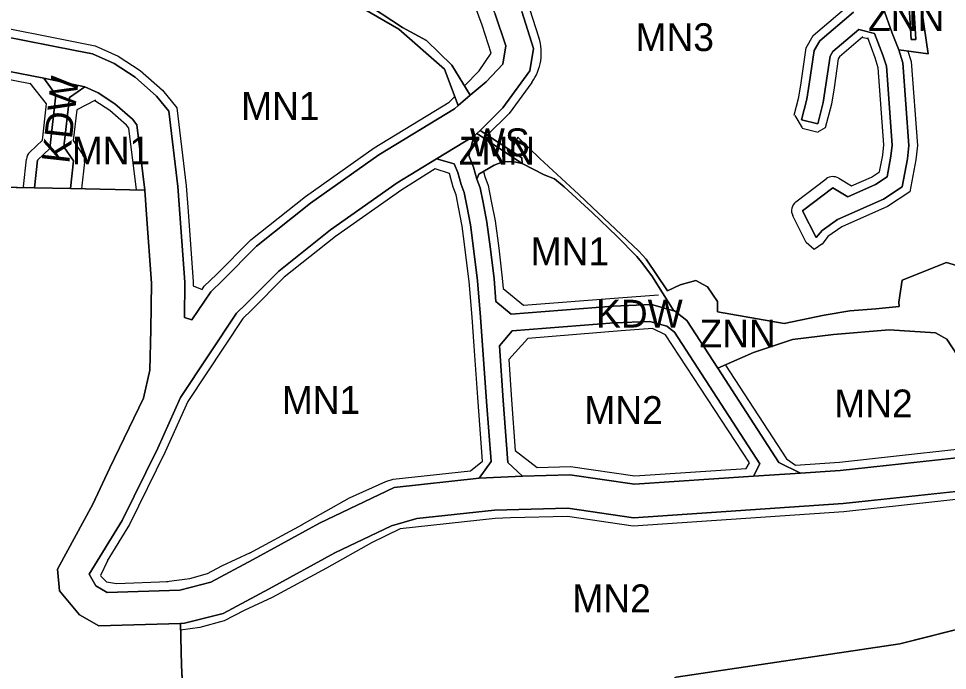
# Model space of a CAD drawing. Extents: x 7417187 to 7419415, y 5539178 to 5540826.
# Drawn here: x 7418734.7 to 7419069, y 5539426.9 to 5539661.6 of the extents above; entities that cross this region are included whole.
import ezdxf

# ---------------------------------------------------------------- set-up
doc = ezdxf.new("R2010")
doc.units = 0
for name, color, linetype in [('linie_rozgraniczajace', 7, 'Continuous'), ('linie_zabudowy_nieprzekraczalne', 7, 'Continuous'), ('linie_zabudowy_obowiazujace', 7, 'Continuous'), ('oznaczenia_przeznaczen', 7, 'Continuous')]:
    doc.layers.add(name, color=color, linetype=linetype)

msp = doc.modelspace()

# ---------------------------------------------------------------- linework, layer by layer
at = {"layer": 'linie_rozgraniczajace'}
for p, q in [((7418915.76, 5539664.18), (7418920.06, 5539650.87)), ((7418910.1, 5539651.81), (7418906.24, 5539663.18)), ((7418721.47, 5539656.75), (7418755.04, 5539650.17)), ((7418909.02, 5539645.17), (7418910.1, 5539651.81)), ((7418920.06, 5539650.87), (7418918.74, 5539642.86)), ((7418755.04, 5539650.17), (7418761.3, 5539648.92)), ((7418761.3, 5539648.92), (7418769.02, 5539645.39)), ((7418743.77, 5539640.15), (7418716.56, 5539645.49)), ((7418769.02, 5539645.39), (7418776.61, 5539640.53)), ((7418902.92, 5539638.89), (7418909.02, 5539645.17)), ((7418776.61, 5539640.53), (7418784.34, 5539633.71)), ((7418918.74, 5539642.86), (7418909.01, 5539629.45)), ((7418758.55, 5539636.99), (7418743.77, 5539640.15)), ((7418763.26, 5539634.83), (7418758.55, 5539636.99)), ((7418897.27, 5539634.04), (7418902.92, 5539638.89)), ((7418769.36, 5539630.92), (7418763.26, 5539634.83)), ((7418784.34, 5539633.71), (7418788.76, 5539628.29)), ((7418892.9, 5539630.28), (7418897.27, 5539634.04)), ((7418775.66, 5539625.36), (7418769.36, 5539630.92)), ((7418891.57, 5539629.14), (7418892.9, 5539630.28)), ((7418788.76, 5539628.29), (7418792.01, 5539601.11)), ((7418864.35, 5539612.52), (7418891.57, 5539629.14)), ((7418909.01, 5539629.45), (7418900.77, 5539621.35)), ((7418777.26, 5539623.4), (7418775.66, 5539625.36)), ((7418780.07, 5539599.87), (7418777.26, 5539623.4)), ((7418899.59, 5539620.2), (7418898.99, 5539619.61)), ((7418900.77, 5539621.35), (7418899.59, 5539620.2)), ((7418898.5, 5539619.31), (7418885.09, 5539611.12)), ((7418898.99, 5539619.61), (7418898.5, 5539619.31)), ((7418839.77, 5539595.13), (7418864.35, 5539612.52)), ((7418885.09, 5539611.12), (7418870.95, 5539602.49)), ((7418655.08, 5539602.38), (7418740.36, 5539600.67)), ((7418740.36, 5539600.67), (7418753.3, 5539600.41)), ((7418753.3, 5539600.41), (7418780.07, 5539599.87)), ((7418792.01, 5539601.11), (7418794.46, 5539566.73)), ((7418870.95, 5539602.49), (7418846.98, 5539585.52)), ((7418780.07, 5539599.87), (7418780.7, 5539591.09)), ((7418780.7, 5539591.09), (7418780.07, 5539599.87)), ((7418820.3, 5539579.65), (7418839.77, 5539595.13)), ((7418780.7, 5539591.09), (7418782.46, 5539566.36)), ((7418782.46, 5539566.36), (7418780.7, 5539591.09)), ((7418846.98, 5539585.52), (7418828.32, 5539570.69)), ((7418808.03, 5539567.3), (7418820.3, 5539579.65)), ((7418828.32, 5539570.69), (7418816.44, 5539558.74)), ((7418794.46, 5539566.73), (7418794.34, 5539553.92)), ((7418803.82, 5539563.26), (7418808.03, 5539567.3)), ((7418782.46, 5539566.36), (7418782.29, 5539549.7)), ((7418782.29, 5539549.7), (7418782.46, 5539566.36)), ((7418797.06, 5539553.11), (7418803.82, 5539563.26)), ((7418816.44, 5539558.74), (7418813.08, 5539555.51)), ((7418813.08, 5539555.51), (7418792.89, 5539525.21)), ((7418794.34, 5539553.92), (7418797.06, 5539553.11)), ((7418782.29, 5539549.7), (7418781.86, 5539535.02)), ((7418781.86, 5539535.02), (7418782.29, 5539549.7)), ((7418781.86, 5539535.02), (7418779.64, 5539524.96)), ((7418779.64, 5539524.96), (7418781.86, 5539535.02)), ((7418779.64, 5539524.96), (7418767.47, 5539499.83)), ((7418767.47, 5539499.83), (7418779.64, 5539524.96)), ((7418792.89, 5539525.21), (7418784.73, 5539506.91)), ((7418784.73, 5539506.91), (7418771.97, 5539480.92)), ((7419030.45, 5539498.89), (7419094.66, 5539505.83)), ((7418767.47, 5539499.83), (7418761.44, 5539486.71)), ((7418761.44, 5539486.71), (7418767.47, 5539499.83)), ((7418900.51, 5539496.09), (7418916.11, 5539496.87)), ((7418916.11, 5539496.87), (7418933.11, 5539497.3)), ((7418933.11, 5539497.3), (7418956.42, 5539493.92)), ((7418956.42, 5539493.92), (7418999.27, 5539496.8)), ((7418999.27, 5539496.8), (7419016.1, 5539497.93)), ((7419016.1, 5539497.93), (7419030.45, 5539498.89)), ((7418869.87, 5539492.74), (7418900.51, 5539496.09)), ((7419100.14, 5539494.37), (7419031.5, 5539486.94)), ((7418842.99, 5539479.9), (7418869.87, 5539492.74)), ((7418761.44, 5539486.71), (7418748.65, 5539463.29)), ((7418748.65, 5539463.29), (7418761.44, 5539486.71)), ((7419031.5, 5539486.94), (7418955.96, 5539481.86)), ((7418905.97, 5539484.62), (7418878, 5539481.56)), ((7418932.4, 5539485.28), (7418905.97, 5539484.62)), ((7418955.96, 5539481.86), (7418932.4, 5539485.28)), ((7418771.97, 5539480.92), (7418760.11, 5539461.57)), ((7418819.09, 5539466.85), (7418842.99, 5539479.9)), ((7418878, 5539481.56), (7418868.88, 5539478.97)), ((7418868.88, 5539478.97), (7418848.46, 5539469.21)), ((7418803.92, 5539458.61), (7418819.09, 5539466.85)), ((7418848.46, 5539469.21), (7418824.83, 5539456.31)), ((7418748.65, 5539463.29), (7418749.38, 5539455.54)), ((7418749.38, 5539455.54), (7418748.65, 5539463.29)), ((7418760.11, 5539461.57), (7418762.44, 5539457.29)), ((7418762.44, 5539457.29), (7418766.5, 5539454.99)), ((7418792.74, 5539455.79), (7418803.92, 5539458.61)), ((7418824.83, 5539456.31), (7418808.32, 5539447.35)), ((7418749.38, 5539455.54), (7418756.53, 5539446.85)), ((7418756.53, 5539446.85), (7418749.38, 5539455.54)), ((7418766.5, 5539454.99), (7418792.74, 5539455.79)), ((7418756.53, 5539446.85), (7418763.51, 5539442.89)), ((7418763.51, 5539442.89), (7418756.53, 5539446.85)), ((7418808.32, 5539447.35), (7418794.41, 5539443.84)), ((7418763.51, 5539442.89), (7418792.9, 5539443.79)), ((7418792.9, 5539443.79), (7418763.51, 5539442.89)), ((7418794.41, 5539443.84), (7418792.9, 5539443.79)), ((7418792.9, 5539443.79), (7418793.33, 5539428.77)), ((7419051.94, 5539436.41), (7419080.39, 5539443.66)), ((7418971.32, 5539424.46), (7419051.94, 5539436.41)), ((7418793.33, 5539428.77), (7418794.01, 5539413.71))]:
    msp.add_line(p, q, dxfattribs=at)
for points in [[(7419047.5, 5539744.86), (7419059.78, 5539708.29), (7419060.96, 5539690.25), (7419059.26, 5539677.84), (7419056.87, 5539667.66), (7419057.67, 5539654.15), (7419055.93, 5539654.12), (7419055.16, 5539667.82), (7419057.85, 5539679.27), (7419059.02, 5539686.28), (7419059.04, 5539692.28), (7419058.46, 5539703.84), (7419057.49, 5539709.17), (7419045.02, 5539745.28)], [(7418897.27, 5539634.04), (7418890.59, 5539644.9), (7418881.51, 5539653.71), (7418872.9, 5539658.41), (7418857.8, 5539668.36), (7418846.8, 5539675.56), (7418812.55, 5539679.73), (7418811.52, 5539682.26), (7418808.62, 5539698.53), (7418791.51, 5539718.25), (7418804.62, 5539739.12), (7418816.66, 5539735.33), (7418826.26, 5539733.2), (7418853.21, 5539731.33), (7418864.01, 5539731.44), (7418870.47, 5539726.74), (7418874.06, 5539718.28), (7418880.65, 5539707.8), (7418891.15, 5539691.67), (7418899.89, 5539677.74), (7418906.24, 5539663.18), (7418910.1, 5539651.81), (7418909.02, 5539645.17), (7418902.92, 5539638.89)], [(7418743.77, 5539640.15), (7418748.05, 5539634.12), (7418745.93, 5539614.83), (7418741.45, 5539610.61), (7418740.36, 5539600.67), (7418655.08, 5539602.38), (7418645.97, 5539602.68), (7418652.71, 5539652.14), (7418658.31, 5539656.29), (7418665.64, 5539654.94), (7418716.56, 5539645.49)], [(7418758.55, 5539636.99), (7418753.03, 5539633.15), (7418751, 5539615.45), (7418754.44, 5539610.34), (7418753.3, 5539600.41), (7418740.36, 5539600.67), (7418741.45, 5539610.61), (7418745.93, 5539614.83), (7418748.05, 5539634.12), (7418743.77, 5539640.15)], [(7418780.07, 5539599.87), (7418753.3, 5539600.41), (7418754.44, 5539610.34), (7418751, 5539615.45), (7418753.03, 5539633.15), (7418758.55, 5539636.99), (7418763.26, 5539634.83), (7418769.36, 5539630.92), (7418775.66, 5539625.36), (7418777.26, 5539623.4)], [(7418915.98, 5539609.46), (7418912.49, 5539610.13), (7418909.02, 5539609.99), (7418905.8, 5539608.84), (7418900.32, 5539605.65), (7418899.63, 5539603.75), (7418898.43, 5539608.09), (7418896.73, 5539612.29), (7418898.5, 5539619.31), (7418898.99, 5539619.61), (7418899.59, 5539620.2)], [(7418911.95, 5539613.98), (7418915.76, 5539611.47), (7418915.98, 5539609.46), (7418899.59, 5539620.2), (7418900.77, 5539621.35)], [(7418899.63, 5539603.75), (7418900.86, 5539600.71), (7418901.87, 5539595.36), (7418903.2, 5539588.32), (7418904.54, 5539578.57), (7418905.8, 5539567.85), (7418906.51, 5539559.76), (7418911.93, 5539555.17), (7418948.71, 5539558.04), (7418962.55, 5539558.6), (7418970.52, 5539556.38), (7418970.73, 5539556.32), (7418975.26, 5539552.89), (7418986.37, 5539535.74), (7419008.39, 5539501.79), (7419016.1, 5539497.93), (7418999.27, 5539496.8), (7419001.54, 5539501.33), (7418970.79, 5539548.74), (7418968.01, 5539550.85), (7418961.85, 5539552.57), (7418949.06, 5539552.05), (7418912.35, 5539549.18), (7418907.72, 5539543.81), (7418909.12, 5539524.11), (7418910.76, 5539501.76), (7418916.11, 5539496.87), (7418900.51, 5539496.09), (7418904.72, 5539502.06), (7418903.13, 5539523.68), (7418900.98, 5539554.12), (7418899.83, 5539567.24), (7418898.59, 5539577.81), (7418897.28, 5539587.36), (7418895.98, 5539594.24), (7418895.07, 5539599.01), (7418893.94, 5539601.82), (7418892.74, 5539606.16), (7418891.45, 5539609.35), (7418885.09, 5539611.12), (7418898.5, 5539619.31), (7418896.73, 5539612.29), (7418898.43, 5539608.09)], [(7418900.51, 5539496.09), (7418869.87, 5539492.74), (7418842.99, 5539479.9), (7418819.09, 5539466.85), (7418803.92, 5539458.61), (7418792.74, 5539455.79), (7418766.5, 5539454.99), (7418762.44, 5539457.29), (7418760.11, 5539461.57), (7418771.97, 5539480.92), (7418784.73, 5539506.91), (7418792.89, 5539525.21), (7418813.08, 5539555.51), (7418816.44, 5539558.74), (7418828.32, 5539570.69), (7418846.98, 5539585.52), (7418870.95, 5539602.49), (7418885.09, 5539611.12), (7418891.45, 5539609.35), (7418892.74, 5539606.16), (7418893.94, 5539601.82), (7418895.07, 5539599.01), (7418895.98, 5539594.24), (7418897.28, 5539587.36), (7418898.59, 5539577.81), (7418899.83, 5539567.24), (7418900.98, 5539554.12), (7418903.13, 5539523.68), (7418904.72, 5539502.06)], [(7418915.98, 5539609.46), (7418923.91, 5539605.39), (7418927.55, 5539603.9), (7418931.03, 5539601.08), (7418941.31, 5539591.7), (7418950.03, 5539583.27), (7418957.27, 5539575.9), (7418958.88, 5539573.93), (7418962.66, 5539568.98), (7418966.47, 5539562.8), (7418970.52, 5539556.38), (7418962.55, 5539558.6), (7418948.71, 5539558.04), (7418911.93, 5539555.17), (7418906.51, 5539559.76), (7418905.8, 5539567.85), (7418904.54, 5539578.57), (7418903.2, 5539588.32), (7418901.87, 5539595.36), (7418900.86, 5539600.71), (7418899.63, 5539603.75), (7418900.32, 5539605.65), (7418905.8, 5539608.84), (7418909.02, 5539609.99), (7418912.49, 5539610.13)], [(7418999.27, 5539496.8), (7418956.42, 5539493.92), (7418933.11, 5539497.3), (7418916.11, 5539496.87), (7418910.76, 5539501.76), (7418909.12, 5539524.11), (7418907.72, 5539543.81), (7418912.35, 5539549.18), (7418949.06, 5539552.05), (7418961.85, 5539552.57), (7418968.01, 5539550.85), (7418970.79, 5539548.74), (7419001.54, 5539501.33)], [(7419094.66, 5539505.83), (7419030.45, 5539498.89), (7419016.1, 5539497.93), (7419008.39, 5539501.79), (7418986.37, 5539535.74), (7418999.27, 5539541.42), (7419013.22, 5539546.11), (7419028.07, 5539547.89), (7419048.04, 5539549.49), (7419064.77, 5539548.4), (7419068.79, 5539546.21), (7419074.65, 5539537.21), (7419084.35, 5539516.01), (7419088.91, 5539515.5)], [(7419080.39, 5539443.66), (7419051.94, 5539436.41), (7418971.32, 5539424.46), (7418967.53, 5539421.53), (7418794.01, 5539413.71), (7418793.33, 5539428.77), (7418792.9, 5539443.79), (7418794.41, 5539443.84), (7418808.32, 5539447.35), (7418824.83, 5539456.31), (7418848.46, 5539469.21), (7418868.88, 5539478.97), (7418878, 5539481.56), (7418905.97, 5539484.62), (7418932.4, 5539485.28), (7418955.96, 5539481.86), (7419031.5, 5539486.94), (7419100.14, 5539494.37), (7419094.9, 5539472.32)]]:
    msp.add_lwpolyline(points, close=True, dxfattribs=at)
for points in [[(7418716.69, 5539683.83), (7418781.07, 5539672.68), (7418800.26, 5539673.95), (7418812.43, 5539674.88), (7418812.55, 5539679.73), (7418846.8, 5539675.56), (7418857.8, 5539668.36), (7418872.9, 5539658.41), (7418881.51, 5539653.71), (7418890.59, 5539644.9), (7418897.27, 5539634.04), (7418892.9, 5539630.28), (7418888.03, 5539643.41), (7418871.51, 5539657.77), (7418856.13, 5539666.67), (7418834.34, 5539671.03), (7418815.62, 5539670.95), (7418801.32, 5539668.85), (7418779.1, 5539665.63), (7418723.54, 5539676.5)], [(7419055.16, 5539667.82), (7419055.93, 5539654.12), (7419057.67, 5539654.15), (7419056.87, 5539667.66)], [(7418856.13, 5539666.67), (7418871.51, 5539657.77), (7418888.03, 5539643.41), (7418892.9, 5539630.28), (7418891.57, 5539629.14), (7418864.35, 5539612.52), (7418839.77, 5539595.13), (7418820.3, 5539579.65), (7418808.03, 5539567.3), (7418803.82, 5539563.26), (7418797.06, 5539553.11), (7418794.34, 5539553.92), (7418794.46, 5539566.73), (7418792.01, 5539601.11), (7418788.76, 5539628.29), (7418784.34, 5539633.71), (7418776.61, 5539640.53), (7418769.02, 5539645.39), (7418761.3, 5539648.92), (7418755.04, 5539650.17), (7418721.47, 5539656.75)], [(7419078.64, 5539570.81), (7419068.73, 5539573.74), (7419052.72, 5539567.45), (7419051.56, 5539559.45), (7419051.66, 5539557.88), (7419043.22, 5539557.04), (7419033.86, 5539556.37), (7419024.63, 5539554.81), (7419010.26, 5539551.76), (7418986.26, 5539556.05), (7418986.2, 5539559.69), (7418982.64, 5539564.96), (7418978.41, 5539567.28), (7418972.8, 5539565.68), (7418968.29, 5539563.63), (7418960.58, 5539575.02), (7418957.91, 5539577.87), (7418941.13, 5539593.73), (7418936.35, 5539598.33), (7418922.24, 5539611.24), (7418914.38, 5539618.88), (7418911.95, 5539613.98), (7418900.77, 5539621.35), (7418909.01, 5539629.45), (7418918.74, 5539642.86), (7418920.06, 5539650.87), (7418915.76, 5539664.18)], [(7419045.89, 5539665.52), (7419049.14, 5539656.4), (7419051.51, 5539650.36), (7419052.98, 5539645.63), (7419055.18, 5539615.97), (7419054.63, 5539611.16), (7419052.78, 5539601), (7419046.05, 5539596.6), (7419029.45, 5539589.29), (7419023.98, 5539585.31), (7419021.74, 5539582.76), (7419016.91, 5539592.41), (7419027.81, 5539600.7), (7419033.16, 5539597.48), (7419043.18, 5539601.9), (7419047.34, 5539604.61), (7419048.7, 5539612.04), (7419049.16, 5539616.09), (7419047.04, 5539644.5), (7419045.82, 5539648.43), (7419042.73, 5539656.3), (7419037.1, 5539657.7), (7419027.79, 5539649.76), (7419026.86, 5539648.11), (7419024.34, 5539631.44), (7419022.34, 5539623.66), (7419016.53, 5539625.15), (7419018.46, 5539632.66), (7419019.3, 5539637.99), (7419021.09, 5539650.09), (7419023.09, 5539653.63), (7419035.19, 5539663.96)], [(7419035.19, 5539663.96), (7419023.09, 5539653.63), (7419021.09, 5539650.09), (7419019.3, 5539637.99), (7419018.46, 5539632.66), (7419016.53, 5539625.15), (7419022.34, 5539623.66), (7419024.34, 5539631.44), (7419026.86, 5539648.11), (7419027.79, 5539649.76), (7419037.1, 5539657.7), (7419042.73, 5539656.3), (7419045.82, 5539648.43), (7419047.04, 5539644.5), (7419049.16, 5539616.09), (7419048.7, 5539612.04), (7419047.34, 5539604.61), (7419043.18, 5539601.9), (7419033.16, 5539597.48), (7419027.81, 5539600.7), (7419016.91, 5539592.41), (7419021.74, 5539582.76), (7419023.98, 5539585.31), (7419029.45, 5539589.29), (7419046.05, 5539596.6), (7419052.78, 5539601), (7419054.63, 5539611.16), (7419055.18, 5539615.97), (7419052.98, 5539645.63), (7419051.51, 5539650.36), (7419062.14, 5539648.91), (7419059.89, 5539663.67)], [(7419059.89, 5539663.67), (7419062.14, 5539648.91), (7419051.51, 5539650.36), (7419049.14, 5539656.4), (7419045.89, 5539665.52)], [(7419074.65, 5539537.21), (7419068.79, 5539546.21), (7419064.77, 5539548.4), (7419048.04, 5539549.49), (7419028.07, 5539547.89), (7419013.22, 5539546.11), (7418999.27, 5539541.42), (7418986.37, 5539535.74), (7418975.26, 5539552.89), (7418970.73, 5539556.32), (7418970.52, 5539556.38), (7418966.47, 5539562.8), (7418962.66, 5539568.98), (7418958.88, 5539573.93), (7418957.27, 5539575.9), (7418950.03, 5539583.27), (7418941.31, 5539591.7), (7418931.03, 5539601.08), (7418927.55, 5539603.9), (7418923.91, 5539605.39), (7418915.98, 5539609.46), (7418915.76, 5539611.47), (7418911.95, 5539613.98), (7418914.38, 5539618.88), (7418922.24, 5539611.24), (7418936.35, 5539598.33), (7418941.13, 5539593.73), (7418957.91, 5539577.87), (7418960.58, 5539575.02), (7418968.29, 5539563.63), (7418972.8, 5539565.68), (7418978.41, 5539567.28), (7418982.64, 5539564.96), (7418986.2, 5539559.69), (7418986.26, 5539556.05), (7419010.26, 5539551.76), (7419024.63, 5539554.81), (7419033.86, 5539556.37), (7419043.22, 5539557.04), (7419051.66, 5539557.88), (7419051.56, 5539559.45), (7419052.72, 5539567.45), (7419068.73, 5539573.74), (7419078.64, 5539570.81)]]:
    msp.add_lwpolyline(points, dxfattribs=at)
at = {"layer": 'linie_zabudowy_nieprzekraczalne'}
for points in [[(7418886.35, 5539727.74), (7418887.4, 5539725.25), (7418893.29, 5539715.88), (7418904.19, 5539699.14), (7418911.22, 5539685.04), (7418918.6, 5539665.17), (7418921.96, 5539654.75)], [(7418904.83, 5539649.22), (7418901.59, 5539659.27), (7418894.69, 5539677.87), (7418888.54, 5539690.18), (7418878.13, 5539706.18), (7418871.39, 5539716.89), (7418868.17, 5539724.49)], [(7419013.88, 5539626.86), (7419015.52, 5539633.27), (7419016.34, 5539638.44), (7419018.2, 5539651.08), (7419020.74, 5539655.57), (7419035.2, 5539667.91)], [(7418721.73, 5539659.8), (7418755.62, 5539653.11), (7418762.24, 5539651.8), (7418770.47, 5539648.04), (7418778.43, 5539642.93), (7418786.51, 5539635.79), (7418791.64, 5539629.51), (7418795, 5539601.4), (7418795.67, 5539592.17), (7418797.47, 5539566.82), (7418797.45, 5539565.35)], [(7419038.63, 5539655.06), (7419030.15, 5539647.83), (7419029.75, 5539647.12), (7419028.2, 5539636.63), (7419027.28, 5539630.84), (7419025.07, 5539622.32)], [(7419034.5, 5539601.35), (7419041.75, 5539604.54), (7419044.62, 5539606.42), (7419045.73, 5539612.48), (7419046.15, 5539616.15), (7419044.08, 5539643.94), (7419043, 5539647.43), (7419040.36, 5539654.64)], [(7419038.6, 5539654.76), (7419040.57, 5539654.46)], [(7418738.78, 5539638.08), (7418716, 5539642.55), (7418665.1, 5539651.99), (7418661.91, 5539652.58)], [(7419054.68, 5539650.28), (7419055.95, 5539646.19), (7419058.2, 5539615.91), (7419057.6, 5539610.72), (7419055.5, 5539599.19), (7419047.49, 5539593.96), (7419030.96, 5539586.68), (7419026.02, 5539583.09), (7419023.95, 5539580.35)], [(7418895.23, 5539637.37), (7418900.4, 5539642.86), (7418904.83, 5539649.22)], [(7418744.72, 5539630.89), (7418738.85, 5539638.39)], [(7418919.4, 5539638.65), (7418911.3, 5539627.48), (7418903.3, 5539619.64)], [(7418800.74, 5539564.04), (7418801.51, 5539565.2), (7418805.93, 5539569.44), (7418818.3, 5539581.89), (7418837.97, 5539597.53), (7418862.71, 5539615.03), (7418889.71, 5539631.52), (7418891.76, 5539633.69)], [(7418743.27, 5539617.81), (7418744.72, 5539630.89)], [(7418762.34, 5539632.25), (7418755.57, 5539628.77)], [(7418777.05, 5539599.93), (7418774.38, 5539622.19), (7418773.49, 5539623.28), (7418767.55, 5539628.52), (7418762.16, 5539631.98)], [(7418755.57, 5539628.77), (7418754.3, 5539617.72)], [(7419016.85, 5539622.31), (7419014.19, 5539626.78)], [(7419022.46, 5539620.54), (7419016.76, 5539622)], [(7419025.07, 5539622.32), (7419022.54, 5539620.85)], [(7418738.71, 5539613.52), (7418743.27, 5539617.81)], [(7418754.3, 5539617.72), (7418757.76, 5539612.58)], [(7418736.39, 5539601.1), (7418737.47, 5539611.04)], [(7418758.42, 5539609.89), (7418757.32, 5539600.33)], [(7418884.66, 5539607.57), (7418872.61, 5539599.99), (7418848.78, 5539583.13), (7418830.32, 5539568.45), (7418818.55, 5539556.61), (7418815.4, 5539553.58), (7418795.53, 5539523.76), (7418787.45, 5539505.64), (7418774.6, 5539479.48), (7418766.56, 5539466.34)], [(7418889.74, 5539605.78), (7418884.66, 5539607.57)], [(7418901.71, 5539502.23), (7418900, 5539525.22), (7418898.71, 5539543.71), (7418897.97, 5539554.09), (7418896.85, 5539566.94), (7418894.83, 5539583.19), (7418894.32, 5539586.88), (7418893.04, 5539593.69), (7418892.18, 5539598.16), (7418891.09, 5539600.86), (7418889.74, 5539605.78)], [(7419014.49, 5539595.6), (7419025.4, 5539603.89)], [(7419029.88, 5539604.13), (7419034.5, 5539601.35)], [(7419018.17, 5539580.97), (7419013.34, 5539590.62)], [(7419024.17, 5539580.59), (7419021.08, 5539578.41), (7419018.17, 5539580.97)], [(7418797.45, 5539565.35), (7418800.74, 5539564.04)], [(7418897.35, 5539498.81), (7418901.71, 5539502.23)], [(7418869.55, 5539495.72), (7418897.35, 5539498.81)], [(7418853.73, 5539489.03), (7418866.8, 5539494.97)], [(7418866.8, 5539494.97), (7418869.55, 5539495.72)], [(7418836.75, 5539479.37), (7418853.73, 5539489.03)], [(7418817.77, 5539469.12), (7418836.87, 5539479.43)], [(7418766.61, 5539466.35), (7418764.2, 5539461.12), (7418764.32, 5539460.78), (7418766.31, 5539458.84), (7418769.91, 5539458.16)], [(7418807.88, 5539464.58), (7418818.11, 5539469.3)], [(7418802.66, 5539461.74), (7418807.88, 5539464.58)], [(7418787.9, 5539458.86), (7418796.29, 5539460.04)], [(7418796.29, 5539460.04), (7418802.66, 5539461.74)], [(7418769.91, 5539458.16), (7418788.48, 5539458.92)]]:
    msp.add_lwpolyline(points, dxfattribs=at)
for centre, radius, start, end in [((7418904.86, 5539649.22), 17.97, 323.9942, 17.9363), ((7418741.47, 5539610.59), 4.03, 133.3136, 173.5563), ((7418754.43, 5539610.34), 4.02, 353.6249, 33.9459), ((7419027.81, 5539600.7), 4, 58.8947, 127.2246), ((7418739.21, 5539600.68), 2.85, 171.5709, 178.6309), ((7419016.93, 5539592.41), 4.01, 127.4265, 206.5674)]:
    msp.add_arc(centre, radius, start, end, dxfattribs=at)
at = {"layer": 'linie_zabudowy_obowiazujace'}
for points in [[(7418901.96, 5539606.6), (7418902.48, 5539604.71), (7418903.75, 5539601.56), (7418904.82, 5539595.92), (7418906.17, 5539588.8), (7418907.52, 5539578.95), (7418908.79, 5539568.16), (7418909.12, 5539564.41)], [(7418909.12, 5539564.41), (7418916.36, 5539558.36)], [(7418916.36, 5539558.36), (7418950.61, 5539561.11), (7418965.07, 5539562.17)], [(7418997.73, 5539501.61), (7418967.56, 5539547.73), (7418962.89, 5539549.98), (7418951.53, 5539549.15), (7418917.92, 5539546.45)], [(7418917.92, 5539546.45), (7418911.08, 5539538.89)], [(7418911.08, 5539538.89), (7418912.11, 5539524.33), (7418913.46, 5539506.02)], [(7418989.08, 5539536.75), (7419011.12, 5539503.06), (7419014.39, 5539500.82)], [(7419014.39, 5539500.82), (7419030.19, 5539501.88), (7419092.9, 5539508.81)], [(7418913.46, 5539506.02), (7418921.32, 5539500.01)], [(7418921.32, 5539500.01), (7418933.29, 5539500.3), (7418956.54, 5539496.94), (7418996.53, 5539499.62)], [(7418996.53, 5539499.62), (7418997.73, 5539501.61)], [(7419099.43, 5539491.41), (7419031.76, 5539483.95), (7418955.85, 5539478.85), (7418932.22, 5539482.27), (7418911.79, 5539481.77)], [(7418911.79, 5539481.77), (7418906.18, 5539481.63), (7418871.98, 5539477.88)], [(7418871.98, 5539477.88), (7418861.68, 5539472.87), (7418845.54, 5539463.66), (7418825.98, 5539453.1), (7418815.91, 5539448.47), (7418808.62, 5539444.7), (7418799.88, 5539442.36), (7418792.97, 5539441.4)]]:
    msp.add_lwpolyline(points, dxfattribs=at)

# ---------------------------------------------------------------- texts
at = {"layer": 'oznaczenia_przeznaczen'}
for s, p in [('ZNN', (7419040.44, 5539657.13)), ('MN3', (7418956.74, 5539649.93)), ('MN1', (7418814.76, 5539625.15)), ('WS', (7418897.1, 5539612.07)), ('MN1', (7418753.82, 5539609.15)), ('ZNN', (7418893.11, 5539609.04)), ('MN1', (7418918.98, 5539572.81)), ('KDW', (7418942.54, 5539550.36)), ('ZNN', (7418979.76, 5539543.19)), ('MN1', (7418829.41, 5539519.28)), ('MN2', (7419028.28, 5539518.03)), ('MN2', (7418938.3, 5539515.65)), ('MN2', (7418934.01, 5539447.84))]:
    msp.add_text(s, height=10, dxfattribs=at).set_placement(p)
msp.add_text('KDW', height=10, rotation=83.5662, dxfattribs=at).set_placement((7418752.86, 5539609.13))

doc.saveas('drawing.dxf')
